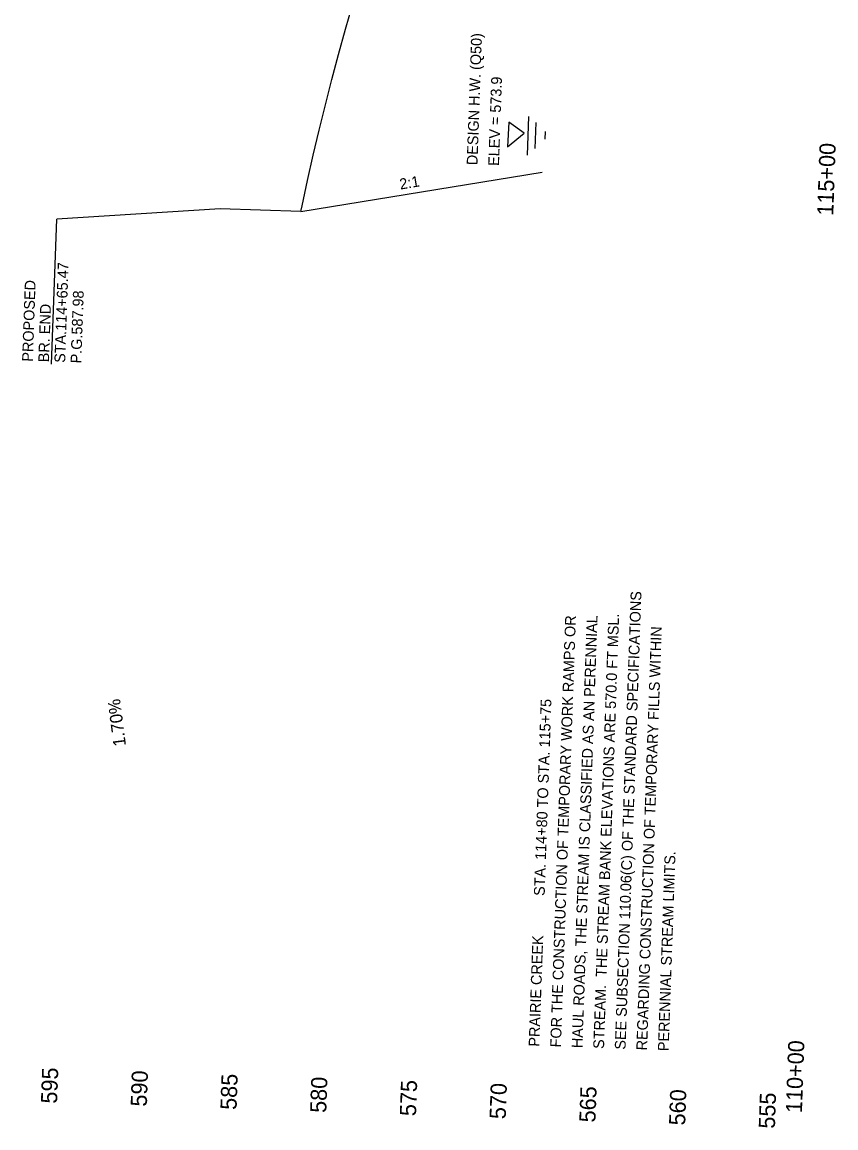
# Model space of a CAD drawing. Extents: x 634032 to 635126, y 289804 to 291423.
# Drawn here: x 634637 to 635091, y 289804 to 290420 of the extents above; entities that cross this region are included whole.
import ezdxf

# ---------------------------------------------------------------- set-up
doc = ezdxf.new("R2010")
doc.units = 0
for name, color, linetype in [('1', 7, 'Continuous'), ('30', 7, 'Continuous'), ('Level 24', 7, 'Continuous'), ('R_Dimension', 7, 'Continuous'), ('R_Draft', 7, 'Continuous'), ('R_Vert Alg', 7, 'Continuous'), ('R_Vert Alg Annot', 7, 'Continuous'), ('Water Level', 7, 'Continuous')]:
    doc.layers.add(name, color=color, linetype=linetype)

msp = doc.modelspace()

# ---------------------------------------------------------------- linework, layer by layer
at = {"layer": 'R_Dimension'}
for p in [(634747.7, 290316.29), (634653.9, 290229.7)]:
    msp.add_line(p, (634656.73, 290310.52), dxfattribs=at)
at = {"layer": 'R_Vert Alg'}
msp.add_line((634792.68, 290314.72), (634747.7, 290316.29), dxfattribs=at)
for points in [[(634792.68, 290314.72), (634793.34, 290317.93), (634796.41, 290332), (634799.61, 290346.06), (634802.94, 290360.12), (634806.4, 290374.17), (634810, 290388.22), (634813.72, 290402.27), (634817.59, 290416.31), (634821.58, 290430.34), (634825.71, 290444.37), (634829.97, 290458.4), (634831.32, 290462.73)], [(634792.68, 290314.72), (634927.03, 290336.75)]]:
    msp.add_lwpolyline(points, dxfattribs=at)
at = {"layer": 'Water Level'}
for p, q in [((634918.84, 290346.15), (634919.59, 290367.7)), ((634908.61, 290364.46), (634907.71, 290350.76)), ((634917.08, 290358.44), (634908.61, 290364.46)), ((634923.28, 290349.87), (634923.79, 290364.35)), ((634928.73, 290355.05), (634928.88, 290359.3)), ((634907.71, 290350.76), (634917.08, 290358.44))]:
    msp.add_line(p, q, dxfattribs=at)

# ---------------------------------------------------------------- texts
at = {"layer": '1'}
for s, p in [('DESIGN H.W. (Q50)', (634891.03, 290340.48)), ('ELEV = 573.9', (634903.02, 290340.06))]:
    msp.add_text(s, height=6, rotation=88, dxfattribs=at).set_placement(p)
at = {"layer": '30'}
for s, p in [('115+00', (635089.2, 290312.32)), ('110+00', (635071.75, 289812.63)), ('595', (634656.92, 289817.89)), ('590', (634706.89, 289816.22)), ('585', (634756.86, 289814.4)), ('580', (634806.83, 289812.73)), ('575', (634856.8, 289810.91)), ('570', (634906.77, 289809.24)), ('565', (634956.74, 289807.42)), ('560', (635006.71, 289805.75)), ('555', (635056.68, 289803.93))]:
    msp.add_text(s, height=9, rotation=88, dxfattribs=at).set_placement(p)
at = {"layer": 'Level 24'}
for s, rotation, p in [('2:1', 9.31433, (634848.15, 290326.97)), ('STA.114+65.47', 88.0044, (634661.42, 290230.43)), ('PROPOSED', 88.0044, (634643.43, 290231.05)), ('P.G.587.98', 88.0044, (634670.42, 290230.11)), ('BR. END', 88.0044, (634652.43, 290230.74))]:
    msp.add_text(s, height=6, rotation=rotation, dxfattribs=at).set_placement(p)
at = {"layer": 'R_Draft'}
for s, p in [('SEE SUBSECTION 110.06(C) OF THE STANDARD SPECIFICATIONS', (634973.51, 289847.96)), ('FOR THE CONSTRUCTION OF TEMPORARY WORK RAMPS OR', (634937.53, 289849.21)), ('HAUL ROADS, THE STREAM IS CLASSIFIED AS AN PERENNIAL', (634949.53, 289848.79)), ('STREAM.  THE STREAM BANK ELEVATIONS ARE 570.0 FT MSL.', (634961.52, 289848.38)), ('REGARDING CONSTRUCTION OF TEMPORARY FILLS WITHIN', (634985.51, 289847.54)), ('STA. 114+80 TO STA. 115+75', (634928.47, 289933.58)), ('PERENNIAL STREAM LIMITS.', (634997.5, 289847.12)), ('PRAIRIE CREEK', (634925.54, 289849.63))]:
    msp.add_text(s, height=6, rotation=88, dxfattribs=at).set_placement(p)
at = {"layer": 'R_Vert Alg Annot'}
msp.add_text('1.70%', height=7, rotation=97.28164, dxfattribs=at).set_placement((634695.34, 290017.37))

doc.saveas('drawing.dxf')
